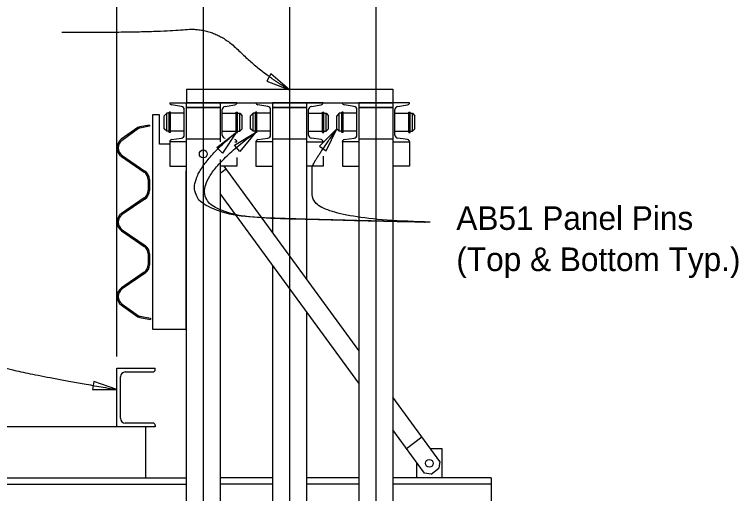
# Model space of a CAD drawing. Extents: x -4.4 to 30.2, y 1.2 to 17.8.
# Drawn here: x 22.971 to 27.691, y 11.153 to 14.28 of the extents above; entities that cross this region are included whole.
import ezdxf

# ---------------------------------------------------------------- set-up
doc = ezdxf.new("R2010")
doc.units = 0
for name, color, linetype in [('CL_Minor', 7, 'Continuous'), ('Dimension', 7, 'Continuous'), ('Miscellaneous', 7, 'Continuous'), ('SteelMisc', 7, 'Continuous'), ('TextStructures', 7, 'Continuous'), ('Wood', 7, 'Continuous')]:
    doc.layers.add(name, color=color, linetype=linetype)

msp = doc.modelspace()

# ---------------------------------------------------------------- linework, layer by layer
at = {"layer": 'CL_Minor'}
for p, q in [((25.3273, 17.6955), (25.3273, 8.1779)), ((24.2019, 16.9098), (24.2019, 8.1779)), ((24.7646, 16.9098), (24.7646, 8.1779))]:
    msp.add_line(p, q, dxfattribs=at)
at = {"layer": 'Dimension'}
msp.add_line((23.6392, 12.0475), (23.6392, 16.1862), dxfattribs=at)
for points in [[(24.7646, 13.7877), (24.6434, 13.8915), (24.6165, 13.8451)], [(24.2896, 13.4124), (24.4158, 13.5099), (24.3282, 13.3755)], [(24.4059, 13.427), (24.5418, 13.5099), (24.4403, 13.3861)], [(25.0733, 13.5334), (24.9601, 13.4206), (25.003, 13.3889)], [(23.6393, 11.8316), (23.4896, 11.8846), (23.4808, 11.8316)]]:
    msp.add_lwpolyline(points, close=True, dxfattribs=at)
for points in [[(23.2801, 14.1636), (23.8871, 14.1622), (24.2761, 14.1999), (24.5801, 13.8981), (24.7646, 13.7877)], [(25.6818, 12.9241), (25.5316, 12.9241), (23.7746, 12.9753), (24.4158, 13.5099)], [(25.6818, 12.9241), (25.5316, 12.9241), (23.8179, 12.9709), (24.5418, 13.5099)], [(25.6818, 12.9241), (24.9132, 12.9431), (24.9111, 13.2537), (24.9111, 13.306), (25.0733, 13.5334)], [(22.1991, 12.2364), (22.456, 12.1739), (22.7708, 12.0046), (23.1472, 11.9163), (23.6393, 11.8316)]]:
    msp.add_open_spline(points, degree=2, dxfattribs=at)
at = {"layer": 'Miscellaneous'}
for p, q in [((23.6392, 11.589), (23.6392, 11.9705)), ((23.6392, 11.9705), (23.8892, 11.9705)), ((23.6939, 11.9467), (23.8736, 11.9467)), ((23.8892, 11.9626), (23.8892, 11.9705)), ((23.6626, 11.6446), (23.6626, 11.9149)), ((23.8736, 11.6128), (23.6939, 11.6128)), ((23.6392, 11.589), (5.6321, 11.589)), ((23.8892, 11.589), (23.6392, 11.589)), ((23.8267, 11.2551), (23.8267, 11.589)), ((23.8892, 11.5969), (23.8892, 11.589))]:
    msp.add_line(p, q, dxfattribs=at)
for centre, major_axis, start_param, end_param in [((23.6939, 11.9149), (0, 0.0318), 0.000005, 1.570796), ((23.8736, 11.9626), (0, -0.0159), 0, 1.570796), ((23.6939, 11.6446), (0, -0.0318), 4.712389, 6.28318), ((23.8736, 11.5969), (0, 0.0159), 4.712389, 6.283185)]:
    msp.add_ellipse(centre, major_axis=major_axis, ratio=0.983193, start_param=start_param, end_param=end_param, dxfattribs=at)
at = {"layer": 'SteelMisc'}
for p, q in [((24.0924, 13.7931), (25.4367, 13.7931)), ((24.0924, 13.7931), (24.0924, 13.7034)), ((25.4367, 13.7931), (25.4367, 13.7034)), ((23.983, 13.7034), (24.0906, 13.7034)), ((24.0597, 13.6801), (23.9954, 13.6897)), ((24.3131, 13.7034), (24.0906, 13.7034)), ((24.0906, 13.7034), (24.0906, 13.4491)), ((24.0924, 13.7034), (25.4367, 13.7034)), ((24.4207, 13.7034), (24.3131, 13.7034)), ((24.3131, 13.7034), (24.3131, 13.4491)), ((24.344, 13.6801), (24.4083, 13.6897)), ((24.5457, 13.7034), (24.6534, 13.7034)), ((24.6225, 13.6801), (24.5582, 13.6897)), ((24.6534, 13.7034), (24.6534, 13.4491)), ((24.8758, 13.7034), (24.6534, 13.7034)), ((24.9834, 13.7034), (24.8758, 13.7034)), ((24.8758, 13.7034), (24.8758, 13.4491)), ((24.9067, 13.6801), (24.971, 13.6897)), ((25.1085, 13.7034), (25.2161, 13.7034)), ((25.1852, 13.6801), (25.1209, 13.6897)), ((25.4385, 13.7034), (25.2161, 13.7034)), ((25.2161, 13.7034), (25.2161, 13.4491)), ((25.5461, 13.7034), (25.4385, 13.7034)), ((25.4385, 13.7034), (25.4385, 13.4491)), ((25.4694, 13.6801), (25.5337, 13.6897)), ((23.9791, 13.5099), (23.9791, 13.6427)), ((23.9879, 13.6427), (23.9791, 13.6427)), ((23.9879, 13.5099), (23.9879, 13.6427)), ((24.0781, 13.4928), (24.0781, 13.6597)), ((24.3131, 13.6716), (24.0906, 13.6716)), ((24.0906, 13.6716), (24.3131, 13.6716)), ((24.3256, 13.4928), (24.3256, 13.6597)), ((24.4158, 13.6427), (24.4246, 13.6427)), ((24.4158, 13.5099), (24.4158, 13.6427)), ((24.4246, 13.5099), (24.4246, 13.6427)), ((24.5418, 13.5099), (24.5418, 13.6427)), ((24.5506, 13.6427), (24.5418, 13.6427)), ((24.5506, 13.5099), (24.5506, 13.6427)), ((24.6409, 13.4928), (24.6409, 13.6597)), ((24.8758, 13.6716), (24.6534, 13.6716)), ((24.6534, 13.6716), (24.8758, 13.6716)), ((24.8883, 13.4928), (24.8883, 13.6597)), ((24.9785, 13.6427), (24.9873, 13.6427)), ((24.9785, 13.5099), (24.9785, 13.6427)), ((24.9873, 13.5099), (24.9873, 13.6427)), ((25.1045, 13.5099), (25.1045, 13.6427)), ((25.1133, 13.6427), (25.1045, 13.6427)), ((25.1133, 13.5099), (25.1133, 13.6427)), ((25.2036, 13.4928), (25.2036, 13.6597)), ((25.4385, 13.6716), (25.2161, 13.6716)), ((25.2161, 13.6716), (25.4385, 13.6716)), ((25.451, 13.4928), (25.451, 13.6597)), ((25.5412, 13.6427), (25.5501, 13.6427)), ((25.5412, 13.5099), (25.5412, 13.6427)), ((25.5501, 13.5099), (25.5501, 13.6427)), ((23.9635, 13.635), (23.9479, 13.6191)), ((23.9479, 13.5334), (23.9479, 13.6191)), ((23.9635, 13.5175), (23.9635, 13.635)), ((23.9791, 13.635), (23.9635, 13.635)), ((24.0781, 13.635), (23.9879, 13.635)), ((24.3256, 13.635), (24.4158, 13.635)), ((24.4246, 13.635), (24.4402, 13.635)), ((24.4402, 13.5175), (24.4402, 13.635)), ((24.4402, 13.635), (24.4558, 13.6191)), ((24.4558, 13.5334), (24.4558, 13.6191)), ((24.5262, 13.635), (24.5106, 13.6191)), ((24.5106, 13.5334), (24.5106, 13.6191)), ((24.5262, 13.5175), (24.5262, 13.635)), ((24.5418, 13.635), (24.5262, 13.635)), ((24.6409, 13.635), (24.5506, 13.635)), ((24.8883, 13.635), (24.9785, 13.635)), ((24.9873, 13.635), (25.0029, 13.635)), ((25.0029, 13.5175), (25.0029, 13.635)), ((25.0029, 13.635), (25.0185, 13.6191)), ((25.0185, 13.5334), (25.0185, 13.6191)), ((25.0889, 13.635), (25.0733, 13.6191)), ((25.0733, 13.5334), (25.0733, 13.6191)), ((25.0889, 13.5175), (25.0889, 13.635)), ((25.1045, 13.635), (25.0889, 13.635)), ((25.2036, 13.635), (25.1133, 13.635)), ((25.451, 13.635), (25.5412, 13.635)), ((25.5501, 13.635), (25.5657, 13.635)), ((25.5657, 13.5175), (25.5657, 13.635)), ((25.5657, 13.635), (25.5813, 13.6191)), ((25.5813, 13.5334), (25.5813, 13.6191)), ((23.8508, 13.5581), (23.7876, 13.5468)), ((23.8522, 13.5497), (23.7891, 13.5384)), ((23.8508, 13.5581), (23.8522, 13.5497)), ((23.7748, 13.5414), (23.6677, 13.4652)), ((23.7797, 13.5344), (23.6726, 13.4582)), ((23.7221, 13.4935), (23.7173, 13.5005)), ((23.7686, 13.5266), (23.7638, 13.5335)), ((23.9635, 13.5175), (23.9479, 13.5334)), ((23.9791, 13.5175), (23.9635, 13.5175)), ((23.9879, 13.5099), (23.9791, 13.5099)), ((24.0781, 13.5175), (23.9879, 13.5175)), ((24.3256, 13.5175), (24.4158, 13.5175)), ((24.4158, 13.5099), (24.4246, 13.5099)), ((24.4246, 13.5175), (24.4402, 13.5175)), ((24.4402, 13.5175), (24.4558, 13.5334)), ((24.5262, 13.5175), (24.5106, 13.5334)), ((24.5418, 13.5175), (24.5262, 13.5175)), ((24.5506, 13.5099), (24.5418, 13.5099)), ((24.6409, 13.5175), (24.5506, 13.5175)), ((24.8883, 13.5175), (24.9785, 13.5175)), ((24.9785, 13.5099), (24.9873, 13.5099)), ((24.9873, 13.5175), (25.0029, 13.5175)), ((25.0029, 13.5175), (25.0185, 13.5334)), ((25.0889, 13.5175), (25.0733, 13.5334)), ((25.1045, 13.5175), (25.0889, 13.5175)), ((25.1133, 13.5099), (25.1045, 13.5099)), ((25.2036, 13.5175), (25.1133, 13.5175)), ((25.451, 13.5175), (25.5412, 13.5175)), ((25.5412, 13.5099), (25.5501, 13.5099)), ((25.5501, 13.5175), (25.5657, 13.5175)), ((25.5657, 13.5175), (25.5813, 13.5334)), ((23.9954, 13.4628), (24.0597, 13.4724)), ((24.0906, 13.4674), (24.3131, 13.4674)), ((24.344, 13.4724), (24.344, 13.4724)), ((24.4083, 13.4628), (24.4083, 13.4628)), ((24.5582, 13.4628), (24.6225, 13.4724)), ((24.6534, 13.4674), (24.8758, 13.4674)), ((24.971, 13.4628), (24.9067, 13.4724)), ((25.1209, 13.4628), (25.1852, 13.4724)), ((25.2161, 13.4674), (25.4385, 13.4674)), ((25.5337, 13.4628), (25.4694, 13.4724)), ((24.0906, 13.4491), (23.983, 13.4491)), ((23.983, 13.4491), (23.983, 13.2901)), ((24.0906, 13.4491), (24.0906, 10.0806)), ((24.3131, 13.4491), (24.3131, 13.4491)), ((24.4081, 13.4491), (24.4207, 13.4491)), ((24.6534, 13.4491), (24.5457, 13.4491)), ((24.5457, 13.4491), (24.5457, 13.2901)), ((24.6534, 13.4491), (24.6534, 12.8576)), ((24.8758, 13.4491), (24.8758, 12.5529)), ((24.8758, 13.4491), (24.9834, 13.4491)), ((24.9834, 13.4491), (24.9834, 13.4491)), ((25.2161, 13.4491), (25.1085, 13.4491)), ((25.1085, 13.4491), (25.1085, 13.2901)), ((25.2161, 13.4491), (25.2161, 10.0806)), ((25.4385, 13.4491), (25.5461, 13.4491)), ((25.4385, 13.4491), (25.4385, 10.0806)), ((25.5461, 13.4491), (25.5461, 13.2901)), ((23.6734, 13.3598), (23.8217, 13.2579)), ((23.6687, 13.3528), (23.817, 13.2508)), ((23.7218, 13.3266), (23.7171, 13.3194)), ((24.3131, 13.3329), (24.3131, 10.0806)), ((24.4207, 13.3473), (24.4207, 13.2901)), ((24.9834, 13.356), (24.9834, 13.2901)), ((23.7689, 13.2943), (23.7641, 13.2871)), ((23.983, 13.2901), (24.0906, 13.2901)), ((24.4207, 13.2901), (24.3131, 13.2901)), ((24.3131, 13.2446), (24.3504, 13.2727)), ((25.2161, 12.0867), (24.3377, 13.2901)), ((24.5457, 13.2901), (24.6534, 13.2901)), ((24.9834, 13.2901), (24.8758, 13.2901)), ((25.1085, 13.2901), (25.2161, 13.2901)), ((25.5461, 13.2901), (25.4385, 13.2901)), ((23.8426, 13.2017), (23.8426, 13.1314)), ((23.8426, 13.1907), (23.851, 13.1907)), ((23.851, 13.2017), (23.851, 13.1314)), ((23.8426, 13.1429), (23.851, 13.1429)), ((23.817, 13.0823), (23.6687, 12.9804)), ((23.8217, 13.0753), (23.6734, 12.9733)), ((25.2161, 11.8734), (24.3131, 13.1106)), ((23.7689, 13.0389), (23.7641, 13.046)), ((23.7218, 13.0066), (23.7171, 13.0137)), ((23.6695, 12.8679), (23.8178, 12.7659)), ((23.6742, 12.875), (23.8225, 12.773)), ((23.7226, 12.8417), (23.7179, 12.8346)), ((23.7696, 12.8094), (23.7649, 12.8023)), ((23.8434, 12.7168), (23.8434, 12.6465)), ((23.8434, 12.7058), (23.8518, 12.7058)), ((23.8518, 12.7168), (23.8518, 12.6465)), ((23.8434, 12.658), (23.8518, 12.658)), ((24.6534, 12.6443), (24.6534, 10.0806)), ((23.8178, 12.5975), (23.6695, 12.4955)), ((23.8225, 12.5904), (23.6742, 12.4884)), ((23.7696, 12.554), (23.7649, 12.5611)), ((23.7226, 12.5217), (23.7179, 12.5288)), ((23.6686, 12.3831), (23.7757, 12.3069)), ((23.6734, 12.3901), (23.7805, 12.3139)), ((23.723, 12.3549), (23.7181, 12.3478)), ((23.7694, 12.3218), (23.7646, 12.3148)), ((24.8758, 12.3396), (24.8758, 10.0806)), ((23.7884, 12.3015), (23.857, 12.2892)), ((23.7898, 12.3099), (23.8584, 12.2976)), ((23.8584, 12.2976), (23.857, 12.2892)), ((25.7443, 11.3629), (25.4385, 11.7819)), ((25.6439, 11.2872), (25.4385, 11.5686)), ((25.527, 11.4474), (25.6274, 11.5231)), ((25.7588, 11.4459), (25.6838, 11.4459)), ((25.7588, 11.2551), (25.7588, 11.4459)), ((25.5922, 11.358), (25.5922, 11.2551)), ((25.7443, 11.3629), (25.7378, 11.3183)), ((25.6877, 11.2805), (25.6439, 11.2872)), ((25.6877, 11.2805), (25.7378, 11.3183)), ((5.1807, 11.2551), (24.0906, 11.2551)), ((24.6534, 11.2551), (24.3131, 11.2551)), ((25.2161, 11.2551), (24.8758, 11.2551)), ((26.0776, 11.2551), (25.4385, 11.2551)), ((26.0776, 11.2551), (26.0776, 10.3648)), ((5.1807, 11.2153), (24.0906, 11.2153)), ((24.6534, 11.2153), (24.3131, 11.2153)), ((25.2161, 11.2153), (24.8758, 11.2153)), ((26.0776, 11.2153), (25.4385, 11.2153))]:
    msp.add_line(p, q, dxfattribs=at)
for centre, major_axis, ratio, start_param, end_param in [((23.9979, 13.7034), (-0.0149, 0), 0.936129, 0, 1.40499), ((24.4058, 13.7034), (0.0149, 0), 0.936129, 4.878195, 6.283185), ((24.5606, 13.7034), (-0.0149, 0), 0.936129, 0, 1.40499), ((24.9685, 13.7034), (0.0149, 0), 0.936129, 4.878195, 6.283185), ((25.1233, 13.7034), (-0.0149, 0), 0.936129, 0, 1.40499), ((25.5313, 13.7034), (0.0149, 0), 0.936129, 4.878195, 6.283185), ((24.0561, 13.6597), (0.022, 0), 0.936129, 0, 1.40499), ((24.3476, 13.6597), (-0.022, 0), 0.936129, 4.878195, 6.283185), ((24.6188, 13.6597), (0.022, 0), 0.936129, 0, 1.40499), ((24.9103, 13.6597), (-0.022, 0), 0.936129, 4.878195, 6.283185), ((25.1815, 13.6597), (0.022, 0), 0.936129, 0, 1.40499), ((25.473, 13.6597), (-0.022, 0), 0.936129, 4.878195, 6.283185), ((23.7931, 13.5149), (0, 0.0324), 0.983191, 0.174592, 0.610846), ((23.7931, 13.5149), (0, 0.0239), 0.983191, 0.174592, 0.610846), ((23.7062, 13.4093), (0, 0.0682), 0.983191, 0.610874, 2.5472), ((23.7062, 13.4093), (0, 0.0597), 0.983191, 0.610874, 2.5472), ((23.9979, 13.4491), (-0.0149, 0), 0.936129, 4.878195, 6.283185), ((24.0561, 13.4928), (0.022, 0), 0.936129, 4.878195, 6.283185), ((24.3476, 13.4928), (-0.022, 0), 0.936129, 6.283185, 7.688175), ((24.4058, 13.4491), (0.0149, 0), 0.936129, 6.283185, 7.688175), ((24.5606, 13.4491), (-0.0149, 0), 0.936129, 4.878195, 6.283185), ((24.6188, 13.4928), (0.022, 0), 0.936129, 4.878195, 6.283185), ((24.9103, 13.4928), (-0.022, 0), 0.936129, 6.283185, 7.688175), ((24.9685, 13.4491), (0.0149, 0), 0.936129, 0, 1.40499), ((25.1233, 13.4491), (-0.0149, 0), 0.936129, 4.878195, 6.283185), ((25.1815, 13.4928), (0.022, 0), 0.936129, 4.878195, 6.283185), ((25.473, 13.4928), (-0.022, 0), 0.936129, 6.283185, 7.688175), ((25.5313, 13.4491), (0.0149, 0), 0.936129, 6.283185, 7.688175), ((24.9685, 13.4491), (0.0149, 0), 0.936129, 6.283185, 6.283185), ((23.7844, 13.2017), (0, 0.0593), 0.983193, 4.712389, 5.688818), ((23.7844, 13.2017), (0, 0.0678), 0.983193, 4.712389, 5.688818), ((23.7844, 13.1314), (0, -0.0593), 0.983193, 0.594367, 1.570796), ((23.7844, 13.1314), (0, -0.0678), 0.983193, 0.594367, 1.570796), ((23.707, 12.9244), (0, 0.0682), 0.983191, 0.610874, 2.5472), ((23.707, 12.9244), (0, 0.0597), 0.983191, 0.610874, 2.5472), ((23.7851, 12.7168), (0, 0.0593), 0.983193, 4.712389, 5.688715), ((23.7851, 12.7168), (0, 0.0678), 0.983193, 4.712389, 5.688715), ((23.7851, 12.6465), (0, -0.0593), 0.983193, 0.594471, 1.570791), ((23.7851, 12.6465), (0, -0.0678), 0.983193, 0.594471, 1.570791), ((23.707, 12.439), (0, 0.0682), 0.983191, 0.594393, 2.530718), ((23.707, 12.439), (0, 0.0597), 0.983191, 0.594393, 2.530718), ((23.7939, 12.3334), (0, -0.0324), 0.983191, 5.67234, 6.108593), ((23.7939, 12.3334), (0, -0.0239), 0.983191, 5.67234, 6.108593)]:
    msp.add_ellipse(centre, major_axis=major_axis, ratio=ratio, start_param=start_param, end_param=end_param, dxfattribs=at)
for centre in [(24.2019, 13.3696), (25.6755, 11.3505)]:
    msp.add_ellipse(centre, major_axis=(0, -0.0259), ratio=0.983193, dxfattribs=at)
at = {"layer": 'Wood'}
msp.add_lwpolyline([(23.983, 13.4332), (23.9166, 13.4332), (23.9166, 13.624), (23.8718, 13.624), (23.8718, 12.2249), (24.0906, 12.2249), (24.0906, 13.2583)], dxfattribs=at)

# ---------------------------------------------------------------- texts
at = {"layer": 'TextStructures'}
for s, p in [('AB51 Panel Pins ', (25.8517, 12.8738)), ('(Top & Bottom Typ.)', (25.8517, 12.6052))]:
    msp.add_text(s, height=0.153845, dxfattribs=at).set_placement(p)

doc.saveas('drawing.dxf')
